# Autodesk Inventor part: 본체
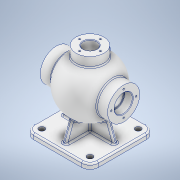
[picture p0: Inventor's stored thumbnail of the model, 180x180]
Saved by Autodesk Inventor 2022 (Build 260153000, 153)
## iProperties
Created: 2024-04
Part Number: 본체
Material: 알루미늄 6061
Document SubType Name: Modeling
Designer: user
Mass: 1526.72 g
Surface Area: 1173.82 cm^2
Volume: 565.453 cm^3
Density: 2.7 g/cm^3
Appearance: 알루미늄 - 평지
Author: user
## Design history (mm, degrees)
sketch "스케치1"
  geometry: L1 (0, 54)-(0, -54); A1 r 54 centre (0, 0) between (0, -54) and (0, 54); 1 further point
  constraints: 2 end point, 2 point on circle, 1 centre point, 1 coincident, 1 vertical
  dimensions: "d0" = 108 diameter of A1; "d1" = 108 distance of L1.start L1.end
revolve "회전1" sketch "스케치1" stored, may be unused: angle "d2" = 90 deg
node "작업 평면1"
sketch "스케치2"
  geometry: L1 (62.5, 62.5)-(-62.5, 62.5); L2 (-62.5, 62.5)-(-62.5, -62.5); L3 (-62.5, -62.5)-(62.5, -62.5); L4 (62.5, -62.5)-(62.5, 62.5); L5 (62.5, 62.5)-(-62.5, -62.5); L6 (-62.5, 62.5)-(62.5, -62.5); 1 further point
  constraints: 12 end point, 2 midpoint, 2 parallel, 1 horizontal, 1 perpendicular
  dimensions: "d4" = 125 distance of L2.end L3.end; "d5" = 125 distance of L1.end L2.end
extrude "돌출1" join sketch "스케치2" distance "d6" = 10; taper "d7" = 0 deg
sketch "스케치3"
  geometry: L1 (-23.202, 0)-(-50.5, -75); L2 (-50.5, -75)-(50.5, -75); L3 (50.5, -75)-(23.202, 0); L4 (23.202, 0)-(-23.202, 0); L5 (62.5, -75)-(-62.5, -75) reference; L6 (-62.5, -85)-(-62.5, -75) reference; 3 further points
  constraints: 8 end point, 3 midpoint, 1 coincident, 1 horizontal, 1 parallel
  dimensions: "d8" = 20 deg angle of L1 L6; "d9" = 12 distance of L5.end L1.end
extrude "돌출2" join sketch "스케치3" stored distance "d10" = 8; taper "d11" = 0 deg
sketch "스케치4"
  geometry: L1 (0, -23.202)-(-75, -50.5); L2 (-75, -50.5)-(-75, 50.5); L3 (-75, 50.5)-(0, 23.202); L4 (0, 23.202)-(0, -23.202); L5 (-75, -4)-(-75, 4) reference; L6 (-85, 62.5)-(-75, 62.5) reference; 3 further points
  constraints: 8 end point, 3 midpoint, 1 coincident, 1 parallel, 1 vertical
  dimensions: "d12" = 20 deg angle of L3 L6; "d13" = 12 distance of L6.end L2.end
extrude "돌출3" join sketch "스케치4" stored distance "d14" = 8; taper "d15" = 0 deg
node "작업 평면2"
sketch "스케치5"
  geometry: C1 r 27 at (0, 0); 1 further point
  constraints: 1 centre point, 1 coincident
  dimensions: "d17" = 54 diameter of C1
extrude "돌출4" join sketch "스케치5" stored distance "d18" = 8; taper "d19" = 0 deg
node "작업 평면3"
sketch "스케치6"
  geometry: C1 r 31 at (0, 0); 1 further point
  constraints: 1 centre point, 1 coincident
  dimensions: "d21" = 62 diameter of C1
extrude "돌출5" join sketch "스케치6" stored distance "d22" = 10; taper "d23" = 0 deg
sketch "스케치7"
  geometry: L1 (0, 44)-(0, -44); A1 r 44 centre (0, 0) between (0, -44) and (0, 44); 1 further point
  constraints: 2 end point, 2 point on circle, 1 centre point, 1 coincident, 1 vertical
  dimensions: "d24" = 88 diameter of A1; "d25" = 88 distance of L1.start L1.end
revolve "회전2" sketch "스케치7" stored, may be unused: angle "d26" = 90 deg
sketch "스케치8"
  geometry: C1 r 13 at (0, 0); 1 further point
  constraints: 1 centre point, 1 coincident
  dimensions: "d27" = 26 diameter of C1
extrude "돌출6" cut sketch "스케치8" stored distance "d28" = 10; taper "d29" = 0 deg
sketch "스케치9"
  geometry: C1 r 17.5 at (0, 0); 1 further point
  constraints: 1 centre point, 1 coincident
  dimensions: "d30" = 35 diameter of C1
extrude "돌출7" cut sketch "스케치9" distance "d31" = 16; taper "d32" = 0 deg
sketch "스케치10"
  geometry: C1 r 17.5 at (0, 0) reference; C2 r 15 at (0, 0); 1 further point
  constraints: 1 centre point, 1 coincident
  dimensions: "d33" = 30 diameter of C2
extrude "돌출8" cut sketch "스케치10" extent not by distance; stored distance "d34" = 0; taper "d35" = 0 deg
fillet "모깎기1" dims "d36" = 16
sketch "스케치11"
  geometry: C1 r 5.5 at (46.5, 46.5); C2 r 5.5 at (46.5, -46.5); C3 r 5.5 at (-46.5, -46.5); C4 r 5.5 at (-46.5, 46.5); A1 r 16 centre (46.5, 46.5) between (62.5, 46.5) and (46.5, 62.5) reference; A2 r 16 centre (46.5, -46.5) between (46.5, -62.5) and (62.5, -46.5) reference; A3 r 16 centre (-46.5, -46.5) between (-62.5, -46.5) and (-46.5, -62.5) reference; A4 r 16 centre (-46.5, 46.5) between (-46.5, 62.5) and (-62.5, 46.5) reference; 1 further point
  constraints: 4 centre point, 4 coincident
  dimensions: "d37" = 11 diameter of C1; "d38" = 11 diameter of C2; "d39" = 11 diameter of C3; "d40" = 11 diameter of C4
extrude "돌출9" cut sketch "스케치11" distance "d41" = 10; taper "d42" = 0 deg
sketch "스케치12"
  geometry: L1 (0, -115)-(0, 95) reference; L2 (-87.5, 0)-(87.5, 0) reference; 2 further points
  constraints: 1 point on line
  dimensions: "d43" = 24 distance from line of L2 point (0, 24)
hole "구멍1" sketch "스케치12" at (0, 24) diameter "d44" = 3.242; stored, may be unused: countersink angle "d48" = 90 deg, drill point angle "d50" = 118 deg; dims "d45" = 12, "d46" = 4, "d47" = 2, "d49" = 15
sketch "스케치13"
  geometry: L1 (-91, 0)-(91, 0) reference; L2 (0, 87.5)-(0, -87.5) reference; 2 further points
  constraints: 1 point on line
  dimensions: "d54" = 20 distance from line of L2 point (-20, 0)
hole "구멍2" sketch "스케치13" at (-20, 0) diameter "d55" = 3.242; stored, may be unused: countersink angle "d59" = 90 deg, drill point angle "d61" = 118 deg; dims "d56" = 9, "d57" = 4, "d58" = 2, "d60" = 11
chamfer "모따기1" distance "d65" = 1; stored, may be unused: second distance "d66" = 2, angle "d67" = 45 deg
fillet "모깎기2" dims "d68" = 3
fillet "모깎기3" dims "d69" = 3
fillet "모깎기4" dims "d70" = 3
fillet "모깎기5" dims "d71" = 3
fillet "모깎기6" dims "d72" = 0.6
fillet "모깎기7" dims "d73" = 3
node "작업 평면4"
sketch "스케치14"
  geometry: L1 (-27, 65)-(27, 65) reference; L2 (0, -115)-(0, 95) reference; L3 (91, 0)-(-91, 0) reference; 2 further points
  constraints: 1 point on line, 1 other
  dimensions: "d75" = 9 distance from line of L1 point (0, 56)
feature "엠보싱1" sketch "스케치14" dims "d0" = 108, "d1" = 108, "d76" = 0.5, "d77" = 0
node "솔리드1"
mirror "미러1"
mirror "미러2"
pattern_circular "원형 패턴1" dims angle "d52" = 360 deg
mirror "미러3"
pattern_circular "원형 패턴2" dims angle "d63" = 360 deg
feature "A9D066F2-1C7D-4E18-AEED-F7BC21143FA4" dims "d44" = 3.242, "d45" = 12, "d46" = 4, "d47" = 2, "d48" = 90 deg, "d49" = 15, "d50" = 118 deg
other parameters: "d3" = -85, "d20" = 65, "d74" = -72.75
